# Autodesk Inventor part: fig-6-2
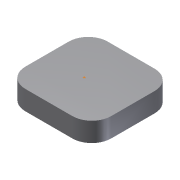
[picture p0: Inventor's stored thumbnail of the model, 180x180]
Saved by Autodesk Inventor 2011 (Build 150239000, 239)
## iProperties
Created: 2004-05
Part Number: fig-6-2
Document SubType Name: Modeling
Designer: CADCIM Technologies
Manufacturer: Standard
Standards Organization: Custom
Density: 1 g/cm^3
Author: CADCIM Technologies
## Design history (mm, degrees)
sketch "Sketch1"
  geometry: L1 (0, 0)-(44.293, 0); L2 (44.293, 0)-(44.293, 42.442); L3 (44.293, 42.442)-(0, 42.442); L4 (0, 42.442)-(0, 0)
  constraints: 8 end point, 2 parallel, 1 horizontal, 1 perpendicular
extrude "Extrusion1" new body sketch "Sketch1" distance "d0" = 10; taper "d1" = 0 deg
fillet "Fillet1" dims "d2" = 10
sketch "Sketch2"
  geometry: 1 further point
sketch "Sketch3"
  geometry: L1 (10, 42.442)-(34.293, 42.442) reference; L2 (0, 10)-(0, 32.442) reference; L3 (34.293, 0)-(10, 0) reference; L4 (44.293, 32.442)-(44.293, 10) reference; A1 r 10 centre (34.293, 32.442) between (44.293, 32.442) and (34.293, 42.442) reference; A2 r 10 centre (10, 32.442) between (10, 42.442) and (0, 32.442) reference; A3 r 10 centre (10, 10) between (0, 10) and (10, 0) reference; A4 r 10 centre (34.293, 10) between (34.293, 0) and (44.293, 10) reference; 1 further point
workpoint "Work Point1"
body "Solid1"
